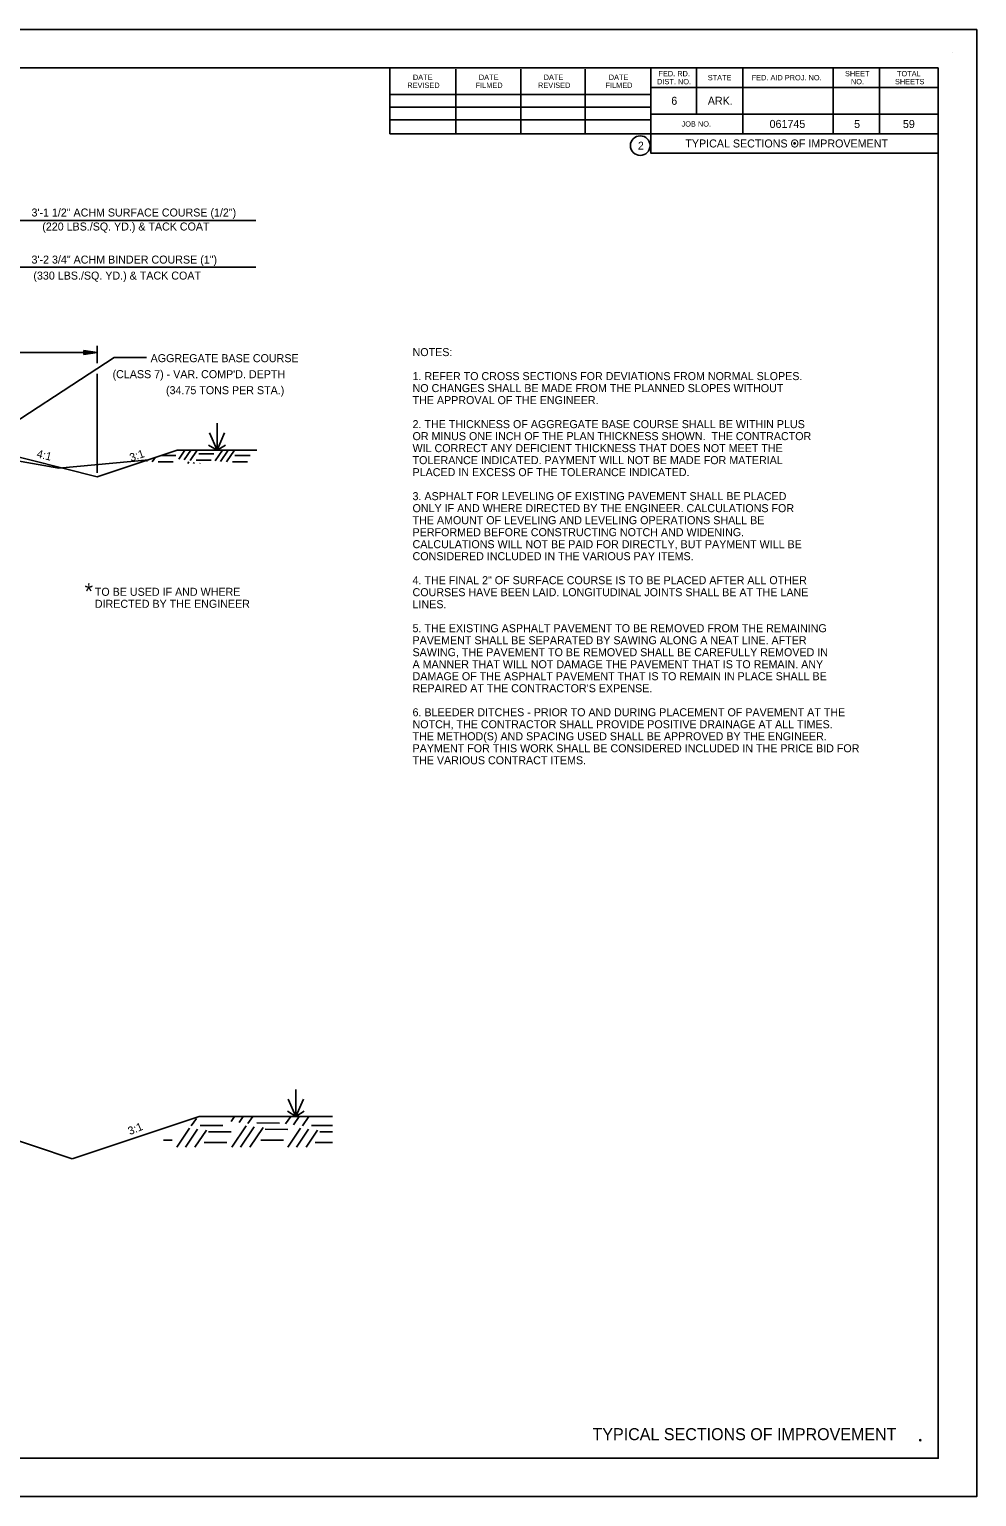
# Model space of a CAD drawing. Extents: x 2478 to 3210, y 439 to 841.
# Drawn here: x 3068.2 to 3210.4, y 438.6 to 658.6 of the extents above; entities that cross this region are included whole.
import ezdxf

# ---------------------------------------------------------------- set-up
doc = ezdxf.new("R2010")
doc.units = 0
for name, color, linetype in [('1', 7, 'Continuous'), ('60', 7, 'Continuous'), ('NO PLOT CELL', 7, 'Continuous'), ('R_Annotation', 7, 'Continuous'), ('R_Dimension', 7, 'Continuous'), ('R_Draft', 7, 'Continuous'), ('R_Exist Surface', 7, 'Continuous')]:
    doc.layers.add(name, color=color, linetype=linetype)

msp = doc.modelspace()

# ---------------------------------------------------------------- linework, layer by layer
at = {"layer": '1'}
for p, q in [((3206.79, 655.12), (3206.79, 655.12)), ((2885.53, 652.81), (3204.6, 652.81)), ((3122.34, 642.93), (3122.34, 652.81)), ((3132.2, 642.93), (3132.2, 652.61)), ((3141.96, 642.93), (3141.96, 652.61)), ((3151.64, 642.93), (3151.64, 652.61)), ((3161.5, 652.81), (3161.5, 640.01)), ((3168.34, 652.81), (3168.34, 645.87)), ((3175.28, 652.81), (3175.28, 642.93)), ((3188.86, 652.81), (3188.86, 642.93)), ((3195.8, 652.81), (3195.8, 642.93)), ((3204.6, 444.35), (3204.6, 652.81)), ((3204.6, 649.87), (3161.5, 649.87)), ((3204.6, 649.89), (3204.6, 649.89)), ((3122.34, 648.79), (3161.5, 648.79)), ((3122.34, 646.93), (3161.5, 646.93)), ((3122.34, 644.99), (3161.5, 644.99)), ((3122.34, 642.93), (3122.34, 644.99)), ((3204.6, 645.87), (3161.5, 645.87)), ((3164.46, 645.87), (3204.6, 645.87)), ((3204.6, 642.93), (3122.34, 642.93)), ((3161.5, 640.01), (3204.6, 640.01)), ((3204.6, 444.35), (2885.53, 444.35))]:
    msp.add_line(p, q, dxfattribs=at)
for points in [[(3210.37, 658.58), (2870.37, 658.58), (2870.37, 438.58), (3210.37, 438.58)], [(2885.53, 444.35), (2885.53, 652.81), (3122.34, 652.81), (3122.34, 642.93), (3161.5, 642.93), (3161.5, 640.01), (3204.6, 640.01), (3204.6, 444.35)]]:
    msp.add_lwpolyline(points, close=True, dxfattribs=at)
msp.add_circle((3159.89, 641.15), 1.47, dxfattribs=at)
at = {"layer": 'NO PLOT CELL'}
for centre in [(3183.05, 641.47), (3201.9, 447.05)]:
    msp.add_circle(centre, 0.1, dxfattribs=at)
at = {"layer": 'R_Annotation'}
for p, q in [((3058.39, 596.5), (3078.39, 591.5)), ((3078.39, 591.5), (3090.39, 595.5)), ((3090.39, 595.5), (3102.39, 595.5)), ((3048.39, 498.01), (3074.68, 489.25)), ((3093.73, 495.6), (3074.68, 489.25)), ((3093.73, 495.6), (3113.73, 495.6))]:
    msp.add_line(p, q, dxfattribs=at)
at = {"layer": 'R_Dimension'}
for p, q in [((3048.39, 629.93), (3102.23, 629.93)), ((3048.39, 622.94), (3102.23, 622.94)), ((3078.39, 610.12), (3050.39, 610.12)), ((3076.39, 610.42), (3078.39, 610.12)), ((3076.39, 610.42), (3076.39, 609.82)), ((3076.39, 610.37), (3078.05, 610.12)), ((3076.39, 610.32), (3077.71, 610.12)), ((3076.39, 610.27), (3077.38, 610.12)), ((3076.39, 610.22), (3077.04, 610.12)), ((3076.39, 610.17), (3076.7, 610.12)), ((3076.39, 609.82), (3078.39, 610.12)), ((3076.39, 610.03), (3077.04, 610.12)), ((3076.39, 609.93), (3077.71, 610.12)), ((3076.39, 609.87), (3078.05, 610.12)), ((3076.39, 609.98), (3077.38, 610.12)), ((3076.39, 610.08), (3076.7, 610.12)), ((3078.39, 608.53), (3078.39, 611.12)), ((3078.39, 592.1), (3078.39, 606.94)), ((3085.79, 593.81), (3085.93, 594.01)), ((3086.68, 593.72), (3087.15, 594.42)), ((3088.01, 594.7), (3090.22, 594.69)), ((3090.67, 594.15), (3091.58, 595.5)), ((3091.47, 594.06), (3092.44, 595.5)), ((3092.36, 593.96), (3093.39, 595.5)), ((3093.64, 594.95), (3095.9, 594.93)), ((3096.12, 593.91), (3097.19, 595.5)), ((3096.92, 593.81), (3098.05, 595.5)), ((3097.81, 593.72), (3099.01, 595.5)), ((3099.09, 594.7), (3101.35, 594.69)), ((3087.57, 593.76), (3089.83, 593.74)), ((3092.02, 593.5), (3092.17, 593.72)), ((3092.88, 593.5), (3092.97, 593.63)), ((3093.25, 594), (3095.51, 593.98)), ((3093.83, 593.5), (3093.86, 593.54)), ((3098.7, 593.76), (3100.96, 593.74)), ((3092.53, 494.19), (3093.29, 495.3)), ((3098.51, 494.83), (3099.03, 495.6)), ((3099.71, 494.69), (3100.32, 495.6)), ((3101.04, 494.55), (3101.75, 495.6)), ((3106.69, 494.47), (3107.45, 495.6)), ((3107.88, 494.33), (3108.74, 495.6)), ((3109.22, 494.19), (3110.17, 495.6)), ((3090.35, 491), (3092.26, 493.83)), ((3091.64, 491), (3093.45, 493.69)), ((3093.07, 491), (3094.79, 493.55)), ((3093.87, 494.25), (3097.26, 494.22)), ((3095.12, 493.3), (3098.51, 493.27)), ((3098.61, 491), (3100.77, 494.19)), ((3099.9, 491), (3101.96, 494.05)), ((3101.33, 491), (3103.3, 493.91)), ((3102.38, 494.61), (3105.77, 494.58)), ((3103.63, 493.66), (3107.02, 493.63)), ((3107.03, 491), (3108.94, 493.83)), ((3108.32, 491), (3110.14, 493.69)), ((3109.75, 491), (3111.47, 493.55)), ((3110.55, 494.25), (3113.73, 494.22)), ((3111.81, 493.3), (3113.73, 493.28)), ((3088.38, 492.03), (3089.67, 492.02)), ((3094.45, 491.69), (3097.85, 491.66)), ((3102.96, 492.05), (3106.36, 492.02)), ((3111.14, 491.69), (3113.73, 491.67))]:
    msp.add_line(p, q, dxfattribs=at)
msp.add_lwpolyline([(3085.8, 609.4), (3080.94, 609.4), (3060.58, 596.07)], dxfattribs=at)
at = {"layer": 'R_Draft'}
for p, q in [((3096.39, 595.5), (3096.39, 599.52)), ((3096.39, 595.5), (3095.13, 596.26)), ((3096.39, 595.5), (3095.25, 598.08)), ((3096.39, 595.5), (3097.53, 598.08)), ((3096.39, 595.5), (3097.64, 596.26)), ((3108.22, 495.6), (3108.22, 499.62)), ((3108.22, 495.6), (3107.08, 498.18)), ((3108.22, 495.6), (3109.36, 498.18)), ((3108.22, 495.6), (3106.96, 496.36)), ((3108.22, 495.6), (3109.48, 496.36))]:
    msp.add_line(p, q, dxfattribs=at)
at = {"layer": 'R_Exist Surface'}
msp.add_lwpolyline([(2971.55, 589.18), (2984.94, 589.49), (2995.98, 592.89), (3003.21, 595.33), (3006.45, 596.34), (3028.39, 596.92), (3047.8, 596.44), (3050.6, 596.33), (3058.49, 595.31), (3072.68, 592.77), (3086.17, 594.04)], dxfattribs=at)

# ---------------------------------------------------------------- texts
at = {"layer": '1'}
for s, height, p in [('DATE', 0.8, (3125.78, 651)), ('DATE', 0.8, (3135.68, 651)), ('DATE', 0.8, (3145.4, 651)), ('DATE', 0.8, (3155.17, 651)), ('FED. RD.', 0.8, (3162.62, 651.54)), ('STATE', 0.8, (3170.02, 650.94)), ('FED. AID PROJ. NO.', 0.8, (3176.61, 650.94)), ('SHEET', 0.8, (3190.61, 651.54)), ('TOTAL', 0.8, (3198.41, 651.54)), ('REVISED', 0.8, (3124.94, 649.8)), ('FILMED', 0.8, (3135.19, 649.8)), ('REVISED', 0.8, (3144.56, 649.8)), ('FILMED', 0.8, (3154.68, 649.8)), ('DIST. NO.', 0.8, (3162.42, 650.34)), ('NO.', 0.8, (3191.5, 650.34)), ('SHEETS', 0.8, (3198.11, 650.34)), ('6', 1.2, (3164.55, 647.27)), ('6', 1.2, (3164.55, 647.27)), ('ARK.', 1.2, (3170.03, 647.27)), ('JOB NO.', 0.8, (3166.09, 644)), ('061745', 1.2, (3179.3, 643.8)), ('5', 1.2, (3191.98, 643.79)), ('59', 1.2, (3199.3, 643.79)), ('2', 1.17, (3159.55, 640.56)), ('TYPICAL SECTIONS OF IMPROVEMENT', 1.2, (3166.66, 640.87))]:
    msp.add_text(s, height=height, dxfattribs=at).set_placement(p)
at = {"layer": '60'}
msp.add_text('TYPICAL SECTIONS OF IMPROVEMENT', height=1.8, dxfattribs=at).set_placement((3152.73, 447.05))
at = {"layer": 'R_Annotation'}
for s, height, p in [('3\'-1 1/2" ACHM SURFACE COURSE (1/2")', 1.197, (3068.56, 630.52)), ('(220 LBS./SQ. YD.) & TACK COAT', 1.197, (3070.18, 628.42)), ('3\'-2 3/4" ACHM BINDER COURSE (1")', 1.2, (3068.56, 623.46)), ('(330 LBS./SQ. YD.) & TACK COAT', 1.2, (3068.84, 621.06)), ('AGGREGATE BASE COURSE', 1.2, (3086.43, 608.68)), ('NOTES:', 1.2, (3125.73, 609.59)), ("(CLASS 7) - VAR. COMP'D. DEPTH", 1.2, (3080.72, 606.28)), ('1. REFER TO CROSS SECTIONS FOR DEVIATIONS FROM NORMAL SLOPES. ', 1.2, (3125.73, 605.99)), ('(34.75 TONS PER STA.)', 1.2, (3088.74, 603.88)), ('NO CHANGES SHALL BE MADE FROM THE PLANNED SLOPES WITHOUT', 1.2, (3125.73, 604.19)), ('THE APPROVAL OF THE ENGINEER.', 1.2, (3125.73, 602.39)), ('2. THE THICKNESS OF AGGREGATE BASE COURSE SHALL BE WITHIN PLUS ', 1.2, (3125.73, 598.79)), ('WIL CORRECT ANY DEFICIENT THICKNESS THAT DOES NOT MEET THE ', 1.2, (3125.73, 595.19)), ('OR MINUS ONE INCH OF THE PLAN THICKNESS SHOWN.  THE CONTRACTOR', 1.2, (3125.73, 596.99)), ('TOLERANCE INDICATED. PAYMENT WILL NOT BE MADE FOR MATERIAL ', 1.2, (3125.73, 593.39)), ('PLACED IN EXCESS OF THE TOLERANCE INDICATED.', 1.2, (3125.73, 591.59)), ('3. ASPHALT FOR LEVELING OF EXISTING PAVEMENT SHALL BE PLACED', 1.2, (3125.73, 587.99)), ('ONLY IF AND WHERE DIRECTED BY THE ENGINEER. CALCULATIONS FOR', 1.2, (3125.73, 586.19)), ('THE AMOUNT OF LEVELING AND LEVELING OPERATIONS SHALL BE ', 1.2, (3125.73, 584.39)), ('PERFORMED BEFORE CONSTRUCTING NOTCH AND WIDENING. ', 1.2, (3125.73, 582.59)), ('CALCULATIONS WILL NOT BE PAID FOR DIRECTLY, BUT PAYMENT WILL BE', 1.2, (3125.73, 580.79)), ('CONSIDERED INCLUDED IN THE VARIOUS PAY ITEMS.', 1.2, (3125.73, 578.99)), ('4. THE FINAL 2" OF SURFACE COURSE IS TO BE PLACED AFTER ALL OTHER ', 1.2, (3125.73, 575.39)), ('*', 2.4, (3076.53, 573.13)), ('TO BE USED IF AND WHERE ', 1.2, (3078.06, 573.65)), ('COURSES HAVE BEEN LAID. LONGITUDINAL JOINTS SHALL BE AT THE LANE', 1.2, (3125.73, 573.59)), ('DIRECTED BY THE ENGINEER', 1.2, (3078.06, 571.85)), ('LINES.', 1.2, (3125.73, 571.79)), ('5. THE EXISTING ASPHALT PAVEMENT TO BE REMOVED FROM THE REMAINING', 1.2, (3125.73, 568.19)), ('PAVEMENT SHALL BE SEPARATED BY SAWING ALONG A NEAT LINE. AFTER ', 1.2, (3125.73, 566.39)), ('SAWING, THE PAVEMENT TO BE REMOVED SHALL BE CAREFULLY REMOVED IN', 1.2, (3125.73, 564.59)), ('A MANNER THAT WILL NOT DAMAGE THE PAVEMENT THAT IS TO REMAIN. ANY', 1.2, (3125.73, 562.79)), ('DAMAGE OF THE ASPHALT PAVEMENT THAT IS TO REMAIN IN PLACE SHALL BE', 1.2, (3125.73, 560.99)), ("REPAIRED AT THE CONTRACTOR'S EXPENSE.", 1.2, (3125.73, 559.19)), ('6. BLEEDER DITCHES - PRIOR TO AND DURING PLACEMENT OF PAVEMENT AT THE', 1.2, (3125.73, 555.59)), ('NOTCH, THE CONTRACTOR SHALL PROVIDE POSITIVE DRAINAGE AT ALL TIMES.  ', 1.2, (3125.73, 553.79)), ('THE METHOD(S) AND SPACING USED SHALL BE APPROVED BY THE ENGINEER.  ', 1.2, (3125.73, 551.99)), ('PAYMENT FOR THIS WORK SHALL BE CONSIDERED INCLUDED IN THE PRICE BID FOR', 1.2, (3125.73, 550.19)), ('THE VARIOUS CONTRACT ITEMS.', 1.2, (3125.73, 548.39))]:
    msp.add_text(s, height=height, dxfattribs=at).set_placement(p)
for s, rotation, p in [('4:1', 345.964, (3069.25, 594.43)), ('3:1', 19.3394, (3083.51, 593.75)), ('3:1', 22.3178, (3083.32, 492.78))]:
    msp.add_text(s, height=1.2, rotation=rotation, dxfattribs=at).set_placement(p)

doc.saveas('drawing.dxf')
